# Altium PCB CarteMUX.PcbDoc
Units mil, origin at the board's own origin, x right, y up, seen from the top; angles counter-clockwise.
Board outline 6000 x 4000 mil, 2 copper layers (Top Layer, Bottom Layer); 13 components, 50 nets, 144 pads, 0 vias.
Unrouted connection lines stored in the file: 37.
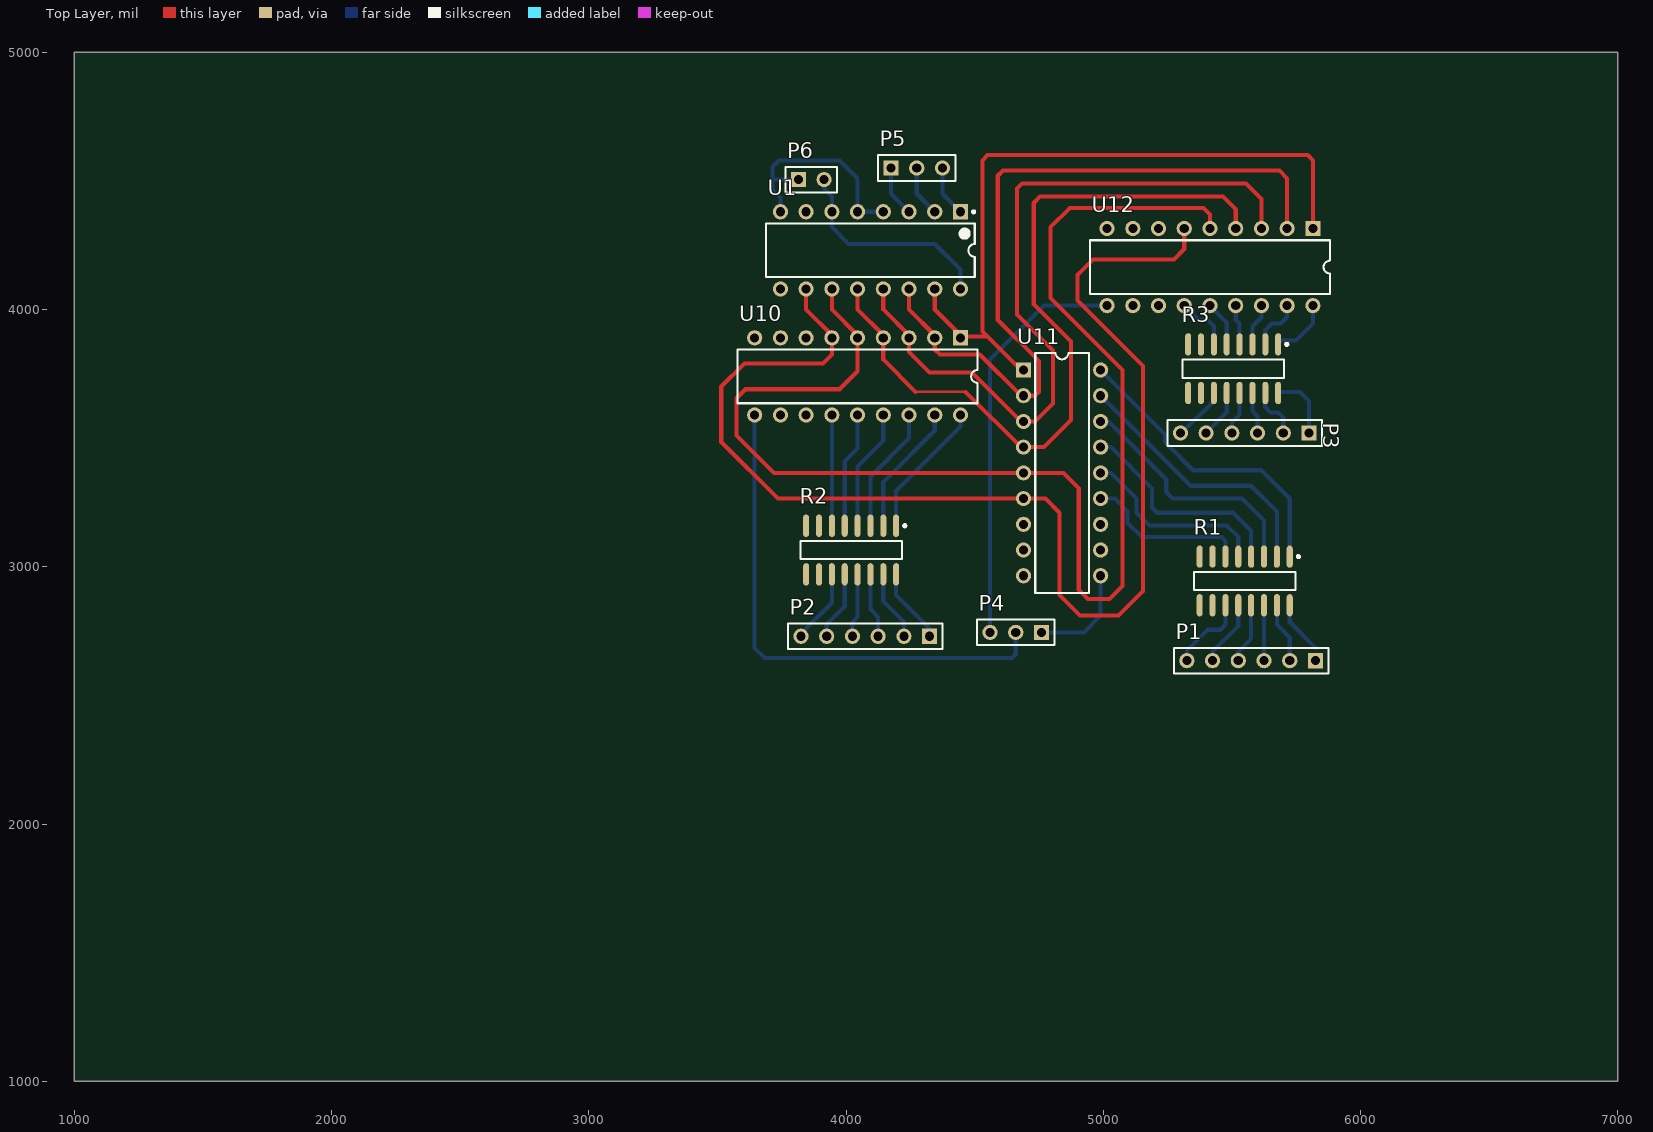
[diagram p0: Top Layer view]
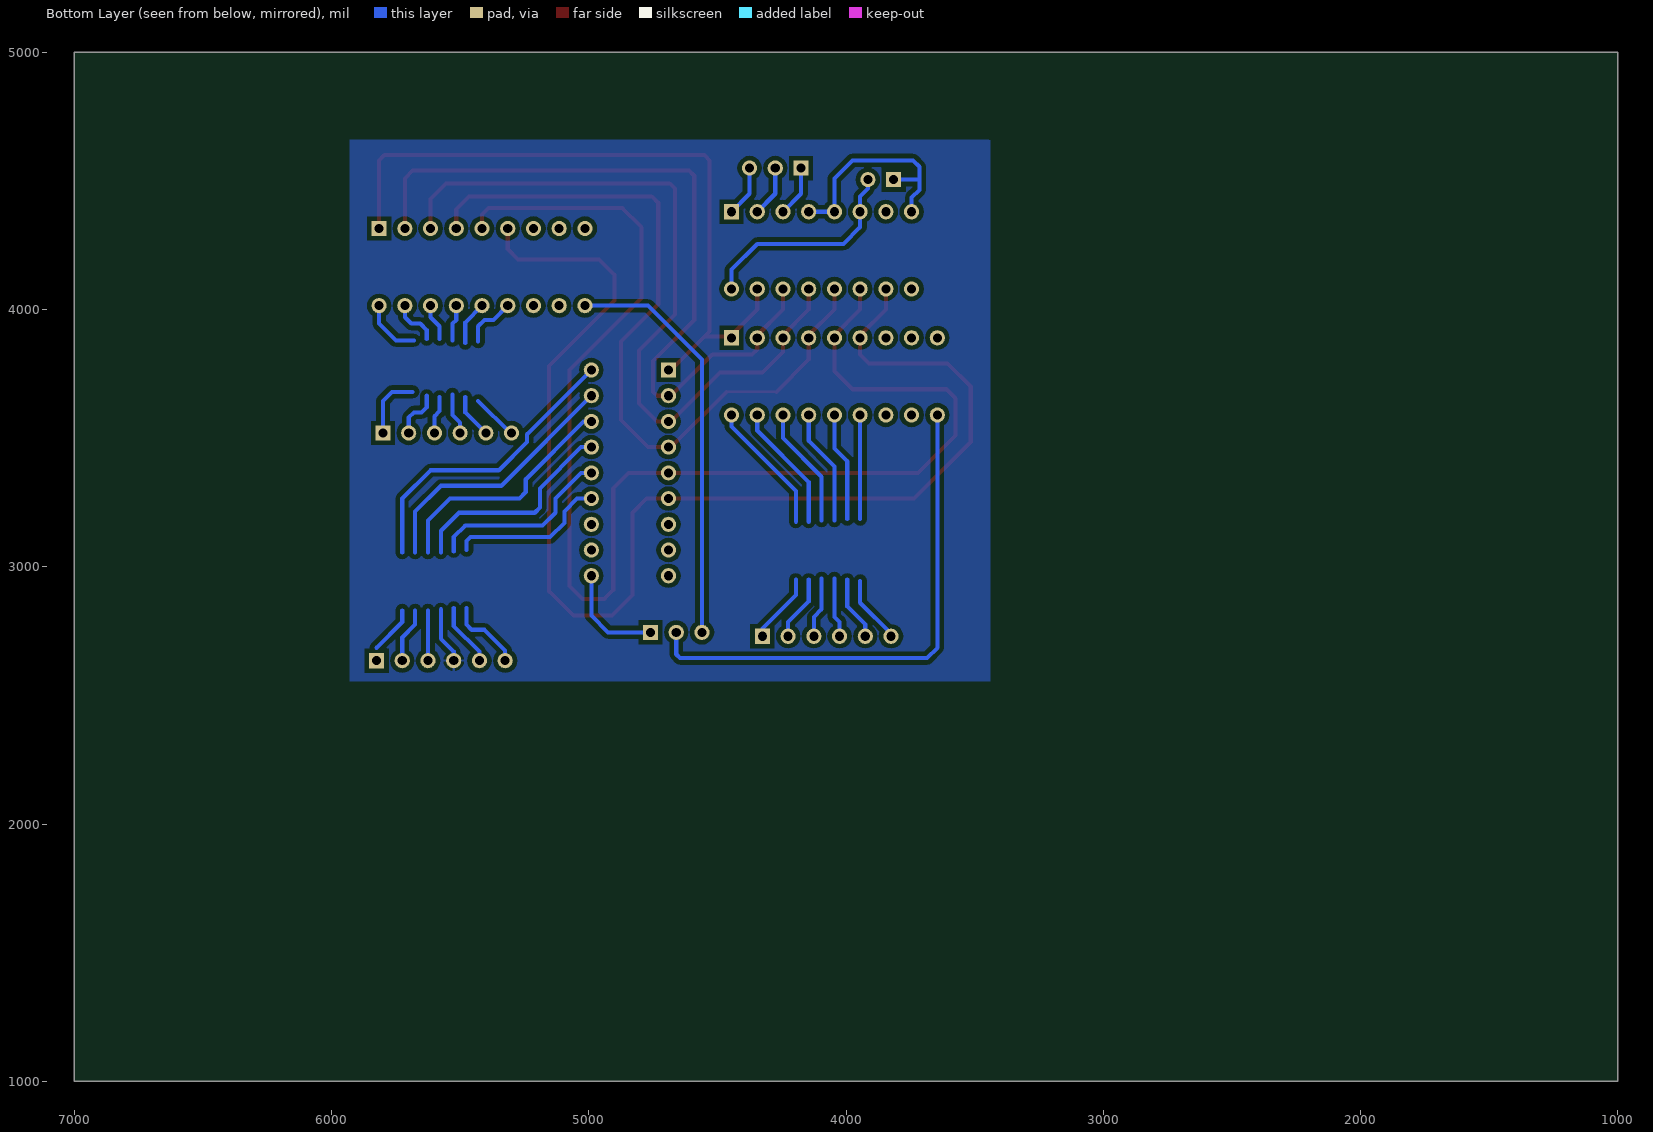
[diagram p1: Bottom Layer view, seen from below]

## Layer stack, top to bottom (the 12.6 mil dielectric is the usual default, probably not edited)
Top Layer: signal copper 1.4
Dielectric: dielectric 12.6, FR-4, Dk 4.8
Bottom Layer: signal copper 1.4

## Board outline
1000,1000 7000,1000 7000,5000 1000,5000

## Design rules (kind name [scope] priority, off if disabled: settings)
Clearance [All] p1: gap=17
PolygonConnect [All] p1: connectstyle=Relief reliefconductorwidth=10 reliefentries=4 polygonreliefangle="90 Angle" airgapwidth=10
RoomDefinition CarteMUX [InComponentClass('CarteMUX')] p1: confinementstyle=ConfineIn formatcopy=TRUE lockcomponents=FALSE outline 1610,-45 5300,-45 5300,1015 1610,1015
RoutingVias [All] p1: holewidth=28 width=50 viastyle="Through Hole" minholewidth=28 minwidth=50 maxholewidth=28 maxwidth=50
SilkscreenOverComponentPads [All] p1: minsilkscreentomaskgap=10
SolderMaskExpansion [All] p1: expansion=4
Width [All] p1: maxlimit=17 minlimit=10 preferedwidth=16
27 further rules are at their usual default settings.

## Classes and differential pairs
component class CarteMUX: U1 U10 U11 U12

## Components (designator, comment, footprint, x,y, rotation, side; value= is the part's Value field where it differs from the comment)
P1 "Header 6" HDR1X6 5825,2635 r180 top
P2 "Header 6" HDR1X6 4325,2730 r180 top
P3 "Header 6" HDR1X6 5800,3520 r180 top
P4 "Header 3" HDR1X3 4760,2745 r180 top
P5 "Header 3" HDR1X3 4175,4550 r0 top
P6 "Header 2" HDR1X2 3815,4505 r0 top
R1 "Res Pack3" SO-16_N 5550,2945 r270 top
R2 "Res Pack3" SO-16_N 4020,3065 r270 top
R3 "Res Pack3" SO-16_N 5505,3770 r270 top
U1 "74AC138PC" N16E 4095,4230 r270 top
U10 "ULQ2803A" DIP18 4045,3740 r180 top
U11 "ULQ2803A" DIP18 4840,3365 r270 top
U12 "ULQ2803A" DIP18 5415,4165 r180 top

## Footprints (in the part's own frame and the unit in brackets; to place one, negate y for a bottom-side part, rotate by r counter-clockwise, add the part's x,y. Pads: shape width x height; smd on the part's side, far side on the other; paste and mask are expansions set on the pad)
DIP18 [mm] "DIP; 18 Leads; Row Spacing 7.62 mm; Pitch 2.54 mm"
  rect 1.5x1.5 hole 0.9: 1(-10.16,-3.81)
  round 1.5 hole 0.9: 2(-7.62,-3.81) 3(-5.08,-3.81) 4(-2.54,-3.81) 5(0,-3.81) 6(2.54,-3.81) 7(5.08,-3.81) 8(7.62,-3.81) 9(10.16,-3.81) 10(10.16,3.81) 11(7.62,3.81) 12(5.08,3.81) 13(2.54,3.81) 14(0,3.81) 15(-2.54,3.81) 16(-5.08,3.81) 17(-7.62,3.81) 18(-10.16,3.81)
  silkscreen extent -11.85,-2.65 11.85,2.65
HDR1X2 [mm] "Connector; Header; 2 Position"
  rect 1.5x1.5 hole 0.9: 1(0,0)
  round 1.5 hole 0.9: 2(2.54,0)
  silkscreen extent -1.27,-1.27 3.81,1.27
HDR1X3 [mm] "Connector; Header; 3 Position"
  rect 1.5x1.5 hole 0.9: 1(0,0)
  round 1.5 hole 0.9: 2(2.54,0) 3(5.08,0)
  silkscreen extent -1.27,-1.27 6.35,1.27
HDR1X6 [mm] "Connector; Header; 6 Position"
  rect 1.5x1.5 hole 0.9: 1(0,0)
  round 1.5 hole 0.9: 2(2.54,0) 3(5.08,0) 4(7.62,0) 5(10.16,0) 6(12.7,0)
  silkscreen extent -1.27,-1.27 13.97,1.27
N16E [mm] "DIP, 16-Leads, Row Spacing 7.62mm, Pitch 2.54mm, Body 19.3x6.35mm"
  rect 1.5x1.5 hole 0.9: 1(-3.81,8.89)
  round 1.5 hole 0.9: 2(-3.81,6.35) 3(-3.81,3.81) 4(-3.81,1.27) 5(-3.81,-1.27) 6(-3.81,-3.81) 7(-3.81,-6.35) 8(-3.81,-8.89) 9(3.81,-8.89) 10(3.81,-6.35) 11(3.81,-3.81) 12(3.81,-1.27) 13(3.81,1.27) 14(3.81,3.81) 15(3.81,6.35) 16(3.81,8.89)
  silkscreen extent -3.93,-10.3 2.65,10.32, body extent -3.6,-10.28 3.6,10.28, height 5.08
SO-16_N [mm] "SOIC, 16-Leads, Body 9.9x3.9mm, Pitch 1.27mm, IPC Medium Density"
  oval 2.2x0.6 smd: 1(-2.4,4.445) 2(-2.4,3.175) 3(-2.4,1.905) 4(-2.4,0.635) 5(-2.4,-0.635) 6(-2.4,-1.905) 7(-2.4,-3.175) 8(-2.4,-4.445) 9(2.4,-4.445) 10(2.4,-3.175) 11(2.4,-1.905) 12(2.4,-0.635) 13(2.4,0.635) 14(2.4,1.905) 15(2.4,3.175) 16(2.4,4.445)
  silkscreen extent -2.52,-5 0.9,5.42, body extent -2,-5 2,5, height 1.75

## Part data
P1 P2 P3: "Header, 6-Pin"
P4 P5: "Header, 3-Pin"
P6: "Header, 2-Pin"
R1 R2 R3: "Isolated Resistor Network"
U1: "1-of-8 Decoder/Multiplexer"
U10 U11 U12: "Eight Darlington Array"

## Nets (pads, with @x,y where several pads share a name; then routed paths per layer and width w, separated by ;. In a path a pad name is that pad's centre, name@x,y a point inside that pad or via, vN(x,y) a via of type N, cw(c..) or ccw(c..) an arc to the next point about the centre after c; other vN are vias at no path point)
NetP1_1: P1.1 R1.16 | length 186.4
  Bottom Layer w16: 5725,2830 5725,2785 5825,2685
NetP1_2: P1.2 R1.15 | length 215.7
  Bottom Layer w16: 5675,2830 5675,2775 5725,2725 P1.2
NetP1_3: P1.3 R1.14 | length 195
  Bottom Layer w16: P1.3 5625,2830
NetP1_4: P1.4 R1.13 | length 220.7
  Bottom Layer w16: P1.4 5525,2670 5575,2720 5575,2835
NetP1_5: P1.5 R1.12 | length 246.4
  Bottom Layer w16: P1.5 5425,2670 5525,2770 5525,2840
NetP1_6: P1.6 R1.11 | length 296.4
  Bottom Layer w16: P1.6 5325,2675 5405,2755 5455,2755 5475,2775 5475,2840
NetP2_1: P2.1 R2.16 | length 273.8
  Bottom Layer w10: P2.1 4325,2760
  Bottom Layer w16: 4195,2950 4195,2890 4325,2760
NetP2_2: P2.2 R2.15 | length 253.1
  Bottom Layer w16: 4145,2950 4145,2865 4225,2785 P2.2
NetP2_3: P2.3 R2.14 | length 237.4
  Bottom Layer w16: 4095,2955 4095,2835 4125,2805 P2.3
NetP2_4: P2.4 R2.13 | length 233.3
  Bottom Layer w16: P2.4 4025,2785 4045,2805 4045,2955
NetP2_5: P2.5 R2.12 | length 249
  Bottom Layer w16: P2.5 3925,2775 3995,2845 3995,2950
NetP2_6: P2.6 R2.11 | length 264.7
  Bottom Layer w16: P2.6 3825,2740 3945,2860 3945,2945
NetP3_1: P3.1 R3.16 | length 254.5
  Bottom Layer w16: 5685,3680 5765,3680 5800,3645 P3.1
NetP3_2: P3.2 R3.15 | length 191.6
  Bottom Layer w16: 5630,3665 5630,3620 5650,3600 5680,3600 5700,3580 P3.2
NetP3_3: P3.3 R3.14 | length 148.3
  Bottom Layer w16: 5580,3660 5580,3605 5600,3585 P3.3
NetP3_4: P3.4 R3.13 | length 162.4
  Bottom Layer w16: P3.4 5500,3560 5530,3590 5530,3670
NetP3_5: P3.5 R3.12 | length 173.1
  Bottom Layer w16: P3.5 5480,3600 5480,3660
NetP3_6: P3.6 R3.11 | length 181.8
  Bottom Layer w10: P3.6 P3.6@5305,3520
  Bottom Layer w16: P3.6@5305,3520 5430,3645
NetP4_1: P4.1 U11.10 | length 411.9
  Bottom Layer w16: P4.1 4925,2745 4990,2810 U11.10
NetP4_2: P4.2 U10.10 | length 2032.8
  Bottom Layer w16: U10.10@3645,3595 3645,2685 3685,2645 4645,2645 4660,2660 P4.2
NetP4_3: P4.3 U12.10 | length 1602
  Bottom Layer w16: P4.3 4560,3805 4770,4015 U12.10
NetP5_1: P5.1 U1.3 | length 199
  Bottom Layer w16: P5.1 4175,4450 U1.3
NetP5_2: P5.2 U1.2 | length 199
  Bottom Layer w16: P5.2 4275,4450 U1.2
NetP5_3: P5.3 U1.1 | length 199
  Bottom Layer w16: P5.3 4375,4450 U1.1
NetP6_1: P6.1 U1.4 U1.5 U1.8 | length 886.8
  Bottom Layer w16: U1.8 3745,4435 3715,4465 3715,4505 ; P6.1 3715,4505 ; U1.4 U1.5 4045,4510 3975,4580 3740,4580 3715,4555 3715,4505
NetP6_2: P6.2 U1.6 U1.16 | length 840.8
  Bottom Layer w16: P6.2 3915,4470 3945,4440 U1.6 3945,4320 4010,4255 4345,4255 4445,4155 U1.16
NetR1_1: R1.1 U11.18 | length 1169.7
  Bottom Layer w16: U11.18 5240,3515 5240,3485 5350,3375 5615,3375 5725,3265 5725,3055
NetR1_2: R1.2 U11.17 | length 1031.4
  Bottom Layer w16: U11.17 5340,3315 5575,3315 5675,3215 5675,3055
NetR1_3: R1.3 U11.16 | length 948.8
  Bottom Layer w16: U11.16 5020,3565 5245,3340 5245,3290 5270,3265 5540,3265 5625,3180 5625,3055
NetR1_4: R1.4 U11.15 | length 848.6
  Bottom Layer w16: U11.15 5030,3465 5190,3305 5190,3230 5210,3210 5505,3210 5575,3140 5575,3055
NetR1_5: R1.5 U11.14 | length 725.8
  Bottom Layer w16: U11.14 5030,3365 5130,3265 5130,3210 5180,3160 5480,3160 5525,3115 5525,3060
NetR1_6: R1.6 U11.13 | length 614.7
  Bottom Layer w16: U11.13 5045,3265 5095,3215 5095,3170 5150,3115 5460,3115 5475,3100 5475,3065
NetR2_1: R2.1 U10.18 | length 523.6
  Bottom Layer w16: 4195,3175 4195,3295 4445,3545 U10.18@4445,3595
NetR2_2: R2.2 U10.17 | length 502.8
  Bottom Layer w16: 4145,3175 4145,3330 4345,3530 U10.17@4345,3595
NetR2_3: R2.3 U10.16 | length 477.1
  Bottom Layer w16: 4095,3180 4095,3350 4245,3500 U10.16@4245,3595
NetR2_4: R2.4 U10.15 | length 456.4
  Bottom Layer w16: 4045,3180 4045,3390 4145,3490 U10.15@4145,3595
NetR2_5: R2.5 U10.14 | length 430.7
  Bottom Layer w16: 3995,3185 3995,3410 4045,3460 U10.14@4045,3595
NetR2_6: R2.6 U10.13 | length 410
  Bottom Layer w16: 3945,3185 U10.13@3945,3595
NetR3_1: R3.1 U12.18 | length 231.9
  Bottom Layer w16: 5680,3880 5750,3880 5815,3945 U12.18
NetR3_2: R3.2 U12.17 | length 185.7
  Bottom Layer w16: 5630,3885 5630,3920 5655,3945 5690,3945 5715,3970 U12.17
NetR3_3: R3.3 U12.16 | length 144.5
  Bottom Layer w16: 5580,3885 5580,3935 5615,3970 U12.16
NetR3_4: R3.4 U12.15 | length 141.2
  Bottom Layer w16: U12.15 5515,3960 5530,3945 5530,3880
NetR3_5: R3.5 U12.14 | length 171.9
  Bottom Layer w16: U12.14 5480,3950 5480,3870
NetR3_6: R3.6 U12.13 | length 208.1
  Bottom Layer w16: U12.13 5370,3960 5405,3960 5430,3935 5430,3875
NetU1_10: U1.10 U10.6 U11.6 U12.6 | length 5011.6
  Top Layer w16: U1.10@3845,4090 3845,4000 U10.6@3945,3900 ; U10.6 3945,3825 3910,3790 3605,3790 3515,3700 3515,3485 3735,3265 4775,3265 4830,3210 4830,2890 4910,2810 5060,2810 5155,2905 5155,3780 4900,4035 4900,4135 4960,4195 5275,4195 5315,4235 U12.6
NetU1_11: U1.11 U10.5 U11.5 U12.5 | length 5267.4
  Top Layer w16: U1.11@3945,4090 3945,4000 U10.5@4045,3900 ; U10.5@4045,3895 4045,3760 3975,3690 3610,3690 3575,3655 3575,3510 3720,3365 4680,3365 4845,3365 4905,3305 4905,2910 4940,2875 5025,2875 5075,2925 5075,3765 4795,4045 4795,4320 4870,4395 5390,4395 5415,4370 U12.5
NetU1_12: U1.12 U10.4 U11.4 U12.4 | length 3031.9
  Top Layer w10: 4270,3680 4465,3680
  Top Layer w16: U1.12@4045,4090 4045,4000 U10.4@4145,3900 ; U10.4@4145,3895 4145,3805 4270,3680 ; 4465,3680 4680,3465 4770,3465 4875,3570 4875,3875 4730,4020 4730,4415 4755,4440 5465,4440 5515,4390 U12.4
NetU1_13: U1.13 U10.3 U11.3 U12.3 | length 2983.4
  Top Layer w16: U1.13@4145,4090 4145,4000 U10.3@4245,3900 ; U10.3@4245,3895 4245,3835 4325,3755 4490,3755 4680,3565 4735,3565 4805,3635 4805,3840 4665,3980 4665,4470 4685,4490 5555,4490 5615,4430 U12.3
NetU1_14: U1.14 U10.2 U11.2 U12.2 | length 3014.2
  Top Layer w16: U1.14@4245,4090 4245,4000 U10.2@4345,3900 ; U10.2@4345,3895 4345,3845 4365,3825 4520,3825 4680,3665 4735,3665 4750,3680 4750,3800 4590,3960 4590,4520 4610,4540 5685,4540 5715,4510 U12.2
NetU1_15: U1.15 U10.1 U11.1 U12.1 | length 2770.1
  Top Layer w16: U1.15 4345,4000 U10.1@4445,3900 ; U10.1@4445,3895 4550,3895 ; U11.1@4680,3765 4550,3895 ; U12.1 5815,4580 5795,4600 4550,4600 4530,4580 4530,3915 4550,3895
pads on no net: R1.7 R1.8 R1.9 R1.10 R2.7 R2.8 R2.9 R2.10 R3.7 R3.8 R3.9 R3.10 U1.7 U1.9 U10.7 U10.8 U10.9 U10.11 U10.12 U11.7 U11.8 U11.9 U11.11 U11.12 U12.7 U12.8 U12.9 U12.11 U12.12
copper on no net: | length 4365
  Bottom Layer w10: 0,19970 0,24335

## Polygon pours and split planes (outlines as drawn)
NetP1_4 on Bottom Layer "masse" (solid, pour order 5): 3445,4660 5930,4660 5930,2555 3440,2555 3440,4655 3440,4665

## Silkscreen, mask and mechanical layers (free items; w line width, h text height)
Mechanical 1:
  lines w16: 3445,2560 3445,2590 3445,4655 3505,4655 5920,4655 5920,2570 ; 3455,2560 5915,2560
